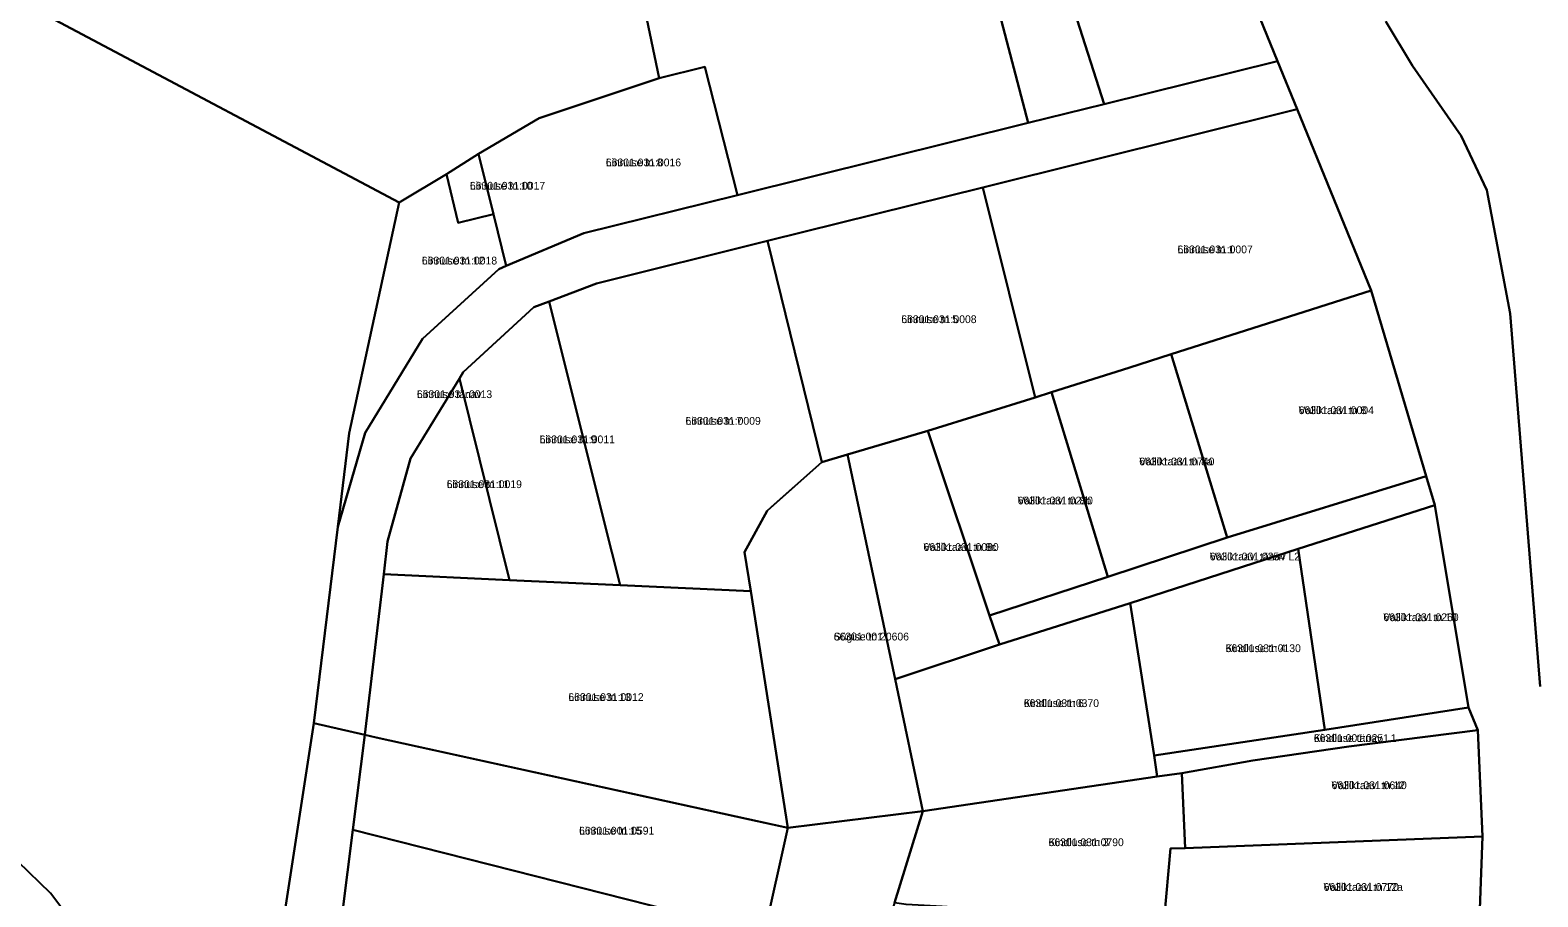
# Model space of a CAD drawing. Extents: x 632278 to 636344, y 6578401 to 6583362.
# Drawn here: x 633424.9 to 633715.5, y 6581093.5 to 6581260.6 of the extents above; entities that cross this region are included whole.
import ezdxf

# ---------------------------------------------------------------- set-up
doc = ezdxf.new("R2010")
doc.units = 0
for name, color, linetype in [('L_AADRESS', 7, 'Continuous'), ('PIIR', 7, 'Continuous'), ('TUNNUS', 7, 'Continuous')]:
    doc.layers.add(name, color=color, linetype=linetype)

msp = doc.modelspace()

# ---------------------------------------------------------------- linework, layer by layer
at = {"layer": 'PIIR'}
for points in [[(633530.04, 6581408.29), (633536.95, 6581405.24), (633539.94, 6581411), (633591.16, 6581389.84), (633593.36, 6581383.16), (633590.56, 6581369.66), (633572.83, 6581358.55), (633582.22, 6581323.44), (633533.6, 6581311.34), (633546.1, 6581251.28), (633522.99, 6581243.6), (633511.27, 6581236.73), (633505.1, 6581232.81), (633495.97, 6581227.32), (633429.59, 6581262.54), (633443.26, 6581348.23), (633469.95, 6581336.04), (633507.65, 6581358.53)], [(633594.13, 6581330.74), (633601.72, 6581333.16), (633597.31, 6581346.79), (633605.38, 6581349.36), (633604.8, 6581351.17), (633635.26, 6581360.98), (633636.62, 6581344.47), (633648.76, 6581342.28), (633647.77, 6581336.32), (633647.98, 6581290.77), (633620.46, 6581282.1), (633631.85, 6581246.28), (633617.25, 6581242.67)], [(633533.6, 6581311.34), (633582.22, 6581323.44), (633593.17, 6581330.43), (633594.13, 6581330.74), (633617.25, 6581242.67), (633561.18, 6581228.75), (633554.9, 6581253.51), (633546.1, 6581251.28)], [(633620.46, 6581282.1), (633647.98, 6581290.77), (633652.61, 6581285.65), (633665.29, 6581254.58), (633631.85, 6581246.28)], [(633665.29, 6581254.58), (633669.07, 6581245.32), (633608.47, 6581230.24), (633566.96, 6581219.91), (633534.02, 6581211.72), (633524.88, 6581208.23), (633521.97, 6581207.13), (633508.29, 6581194.61), (633507.58, 6581193.43), (633498.14, 6581177.99), (633493.75, 6581162.01), (633493, 6581155.69), (633491.91, 6581146.45), (633489.35, 6581124.69), (633479.55, 6581126.98), (633484.15, 6581164.83), (633489.46, 6581182.96), (633500.5, 6581201.02), (633515.22, 6581214.51), (633516.58, 6581215.09), (633531.58, 6581221.42), (633561.18, 6581228.75), (633617.25, 6581242.67), (633631.85, 6581246.28)], [(633511.27, 6581236.73), (633522.99, 6581243.6), (633546.1, 6581251.28), (633554.9, 6581253.51), (633561.18, 6581228.75), (633531.58, 6581221.42), (633516.58, 6581215.09), (633514.15, 6581225.05)], [(633608.47, 6581230.24), (633669.07, 6581245.32), (633683.34, 6581210.34), (633644.81, 6581198.1), (633636.63, 6581195.49), (633621.73, 6581190.75), (633618.59, 6581189.77)], [(633511.27, 6581236.73), (633514.15, 6581225.05), (633507.35, 6581223.38), (633505.1, 6581232.81)], [(633505.1, 6581232.81), (633507.35, 6581223.38), (633514.15, 6581225.05), (633516.58, 6581215.09), (633515.22, 6581214.51), (633500.5, 6581201.02), (633489.46, 6581182.96), (633484.15, 6581164.83), (633486.35, 6581182.89), (633495.97, 6581227.32)], [(633608.47, 6581230.24), (633618.59, 6581189.77), (633597.87, 6581183.32), (633582.39, 6581178.75), (633577.48, 6581177.25), (633566.96, 6581219.91)], [(633524.88, 6581208.23), (633534.02, 6581211.72), (633566.96, 6581219.91), (633577.48, 6581177.25), (633566.9, 6581167.9), (633562.58, 6581159.93), (633563.76, 6581152.4), (633538.55, 6581153.57), (633535.38, 6581166.26)], [(633524.88, 6581208.23), (633535.38, 6581166.26), (633538.55, 6581153.57), (633517.27, 6581154.56), (633507.58, 6581193.43), (633508.29, 6581194.61), (633521.97, 6581207.13)], [(633655.56, 6581162.73), (633644.81, 6581198.1), (633683.34, 6581210.34), (633693.97, 6581174.56)], [(633621.73, 6581190.75), (633636.63, 6581195.49), (633644.81, 6581198.1), (633655.56, 6581162.73), (633632.56, 6581155.2)], [(633507.58, 6581193.43), (633517.27, 6581154.56), (633493, 6581155.69), (633493.75, 6581162.01), (633498.14, 6581177.99)], [(633597.87, 6581183.32), (633618.59, 6581189.77), (633621.73, 6581190.75), (633632.56, 6581155.2), (633609.76, 6581147.75)], [(633597.87, 6581183.32), (633609.76, 6581147.75), (633611.69, 6581142.12), (633591.59, 6581135.42), (633582.39, 6581178.75)], [(633566.9, 6581167.9), (633567.73, 6581168.64), (633577.48, 6581177.25), (633582.39, 6581178.75), (633591.59, 6581135.42), (633596.92, 6581110.03), (633570.9, 6581106.78), (633563.76, 6581152.4), (633562.58, 6581159.93)], [(633609.76, 6581147.75), (633632.56, 6581155.2), (633655.56, 6581162.73), (633693.97, 6581174.56), (633695.62, 6581168.99), (633669.27, 6581160.58), (633636.87, 6581150.11), (633611.69, 6581142.12)], [(633669.27, 6581160.58), (633695.62, 6581168.99), (633702.13, 6581129.97), (633674.44, 6581125.7)], [(633669.27, 6581160.58), (633674.44, 6581125.7), (633641.51, 6581120.75), (633636.87, 6581150.11)], [(633493, 6581155.69), (633517.27, 6581154.56), (633538.55, 6581153.57), (633563.76, 6581152.4), (633570.9, 6581106.78), (633491.52, 6581124.18), (633489.35, 6581124.69), (633491.91, 6581146.45)], [(633591.59, 6581135.42), (633611.69, 6581142.12), (633636.87, 6581150.11), (633641.51, 6581120.75), (633642.1, 6581116.71), (633596.92, 6581110.03)], [(633660.51, 6581119.79), (633646.84, 6581117.35), (633642.1, 6581116.71), (633641.51, 6581120.75), (633674.44, 6581125.7), (633702.13, 6581129.97), (633703.93, 6581125.62), (633679.02, 6581122.48)], [(633479.55, 6581126.98), (633489.35, 6581124.69), (633487.08, 6581106.41), (633479.68, 6581047.76), (633480.39, 6581036.99), (633477.75, 6581025.98), (633453.95, 6581022.36), (633453.46, 6581037.79), (633452.38, 6581042.1), (633462.73, 6581045.47), (633466.5, 6581050.34), (633468.58, 6581055.98)], [(633570.9, 6581106.78), (633566.37, 6581086.29), (633487.08, 6581106.41), (633489.35, 6581124.69), (633491.52, 6581124.18), (633563.52, 6581108.4)], [(633647.5, 6581102.88), (633646.84, 6581117.35), (633660.51, 6581119.79), (633679.02, 6581122.48), (633703.93, 6581125.62), (633704.83, 6581105.14)], [(633591.48, 6581092.36), (633596.92, 6581110.03), (633642.1, 6581116.71), (633646.84, 6581117.35), (633647.5, 6581102.88), (633644.68, 6581102.79), (633643.43, 6581089.17), (633629.15, 6581089.76), (633600.67, 6581091.61), (633593.68, 6581092.04)], [(633570.9, 6581106.78), (633596.92, 6581110.03), (633591.48, 6581092.36), (633586.47, 6581076.99), (633584.3, 6581069.92), (633581.34, 6581057.94), (633579.2, 6581049.45), (633575.06, 6581037.47), (633569.68, 6581025.3), (633559.57, 6581000.86), (633553.49, 6581003.89), (633560.94, 6581024.97), (633571.45, 6581056.88), (633577.47, 6581076.82), (633576.86, 6581083.62), (633566.37, 6581086.29)], [(633553.49, 6581003.89), (633480.39, 6581036.99), (633479.68, 6581047.76), (633487.08, 6581106.41), (633566.37, 6581086.29), (633576.86, 6581083.62), (633577.47, 6581076.82), (633571.45, 6581056.88), (633560.94, 6581024.97)], [(633643.43, 6581089.17), (633644.68, 6581102.79), (633647.5, 6581102.88), (633704.83, 6581105.14), (633704.01, 6581084.13), (633656.24, 6581087.86)]]:
    msp.add_lwpolyline(points, close=True, dxfattribs=at)
for points in [[(633615.05, 6580822.36), (633621.12, 6580851.71), (633622.34, 6580857.15), (633626.87, 6580874.69), (633634.82, 6580899.19), (633637.15, 6580905.29), (633644.15, 6580924.96), (633654.74, 6580949.86), (633659.12, 6580958.62), (633670.46, 6580981.21), (633685.73, 6581012.34), (633696.55, 6581044.87), (633698.45, 6581049.32), (633703.29, 6581076.27), (633704.01, 6581084.13), (633704.83, 6581105.14), (633703.93, 6581125.62), (633702.13, 6581129.97), (633695.62, 6581168.99), (633693.97, 6581174.56), (633683.34, 6581210.34), (633669.07, 6581245.32), (633665.29, 6581254.58), (633652.61, 6581285.65)], [(633429.59, 6581262.54), (633495.97, 6581227.32), (633486.35, 6581182.89), (633484.15, 6581164.83), (633479.55, 6581126.98), (633468.58, 6581055.98), (633466.5, 6581050.34), (633462.73, 6581045.47), (633452.38, 6581042.1), (633448.23, 6581041.03), (633447.22, 6581046.01), (633445.44, 6581051.35), (633441.07, 6581059.91), (633436.69, 6581077.69), (633434.26, 6581086.91), (633428.78, 6581094.18), (633422.55, 6581100.22)], [(633715.89, 6581134.06), (633710.11, 6581205.96), (633705.62, 6581229.72), (633700.7, 6581240.2), (633691.29, 6581253.68), (633686.15, 6581262.24)], [(633686.15, 6581262.24), (633691.29, 6581253.68), (633700.7, 6581240.2), (633705.62, 6581229.72), (633710.11, 6581205.96), (633715.89, 6581134.06)]]:
    msp.add_lwpolyline(points, dxfattribs=at)

# ---------------------------------------------------------------- texts
at = {"layer": 'L_AADRESS'}
for s, p in [('Linnuse tn 8', (633535.82, 6581234.3)), ('Linnuse tn 10', (633509.62, 6581229.81)), ('Linnuse tn 12', (633500.36, 6581215.38)), ('Linnuse tn 1', (633646.02, 6581217.54)), ('Linnuse tn 5', (633592.78, 6581204.08)), ('Linnuse tänav', (633499.4, 6581189.63)), ('Vallikraavi tn 8', (633669.37, 6581186.54)), ('Linnuse tn 7', (633551.18, 6581184.49)), ('Linnuse tn 9', (633523.06, 6581180.92)), ('Vallikraavi tn 8a', (633638.64, 6581176.66)), ('Linnuse tn 11', (633505.14, 6581172.28)), ('Vallikraavi tn 8b', (633615.21, 6581169.13)), ('Vallikraavi tn 8c', (633597.04, 6581160.16)), ('Vallikraavi tänav L2', (633652.24, 6581158.34)), ('Vallikraavi tn 10', (633685.7, 6581146.63)), ('Sügise tn 2', (633579.75, 6581142.91)), ('Kindluse tn 4', (633655.29, 6581140.66)), ('Linnuse tn 13', (633528.6, 6581131.24)), ('Kindluse tn 6', (633616.38, 6581130.07)), ('Kindluse tänav L1', (633672.29, 6581123.34)), ('Vallikraavi tn 12', (633675.71, 6581114.25)), ('Linnuse tn 15', (633530.66, 6581105.49)), ('Kindluse tn 3', (633621.16, 6581103.26)), ('Vallikraavi tn 12a', (633674.18, 6581094.63))]:
    msp.add_text(s, height=1.5, dxfattribs=at).set_placement(p)
at = {"layer": 'TUNNUS'}
for s, p in [('66301:031:0016', (633535.82, 6581234.3)), ('66301:031:0017', (633509.62, 6581229.81)), ('66301:031:0018', (633500.36, 6581215.38)), ('66301:031:0007', (633646.02, 6581217.54)), ('66301:031:0008', (633592.78, 6581204.08)), ('66301:031:0013', (633499.4, 6581189.63)), ('66301:031:0004', (633669.37, 6581186.54)), ('66301:031:0009', (633551.18, 6581184.49)), ('66301:031:0011', (633523.06, 6581180.92)), ('66301:031:0740', (633638.64, 6581176.66)), ('66301:031:0019', (633505.14, 6581172.28)), ('66301:031:0220', (633615.21, 6581169.13)), ('66301:031:0080', (633597.04, 6581160.16)), ('66301:001:0254', (633652.24, 6581158.34)), ('66301:031:0260', (633685.7, 6581146.63)), ('66301:001:0606', (633579.75, 6581142.91)), ('66301:031:0130', (633655.29, 6581140.66)), ('66301:031:0012', (633528.6, 6581131.24)), ('66301:031:0370', (633616.38, 6581130.07)), ('66301:001:0251', (633672.29, 6581123.34)), ('66301:031:0640', (633675.71, 6581114.25)), ('66301:001:0591', (633530.66, 6581105.49)), ('66301:031:0790', (633621.16, 6581103.26)), ('66301:031:0770', (633674.18, 6581094.63))]:
    msp.add_text(s, height=1.5, dxfattribs=at).set_placement(p)

doc.saveas('drawing.dxf')
